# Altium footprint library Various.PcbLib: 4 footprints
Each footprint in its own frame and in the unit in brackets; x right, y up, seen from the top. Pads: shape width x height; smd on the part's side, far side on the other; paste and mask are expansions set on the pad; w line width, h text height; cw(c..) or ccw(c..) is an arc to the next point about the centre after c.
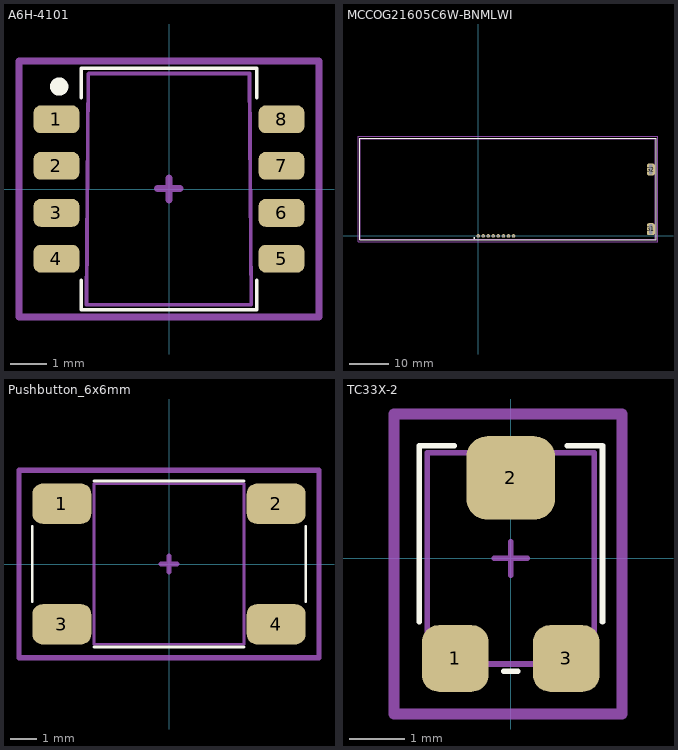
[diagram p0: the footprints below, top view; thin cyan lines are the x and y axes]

## A6H-4101 [mm]
pads (8):
  rrect50% 1.25x0.76 smd paste+0 mask+0.1: 1(-3.075,1.905) 2(-3.075,0.635) 3(-3.075,-0.653) 4(-3.075,-1.905) 5(3.075,-1.905) 6(3.075,-0.653) 7(3.075,0.635) 8(3.075,1.905)
Top Overlay:
  circle w0.3: c-3,2.8 r0.1
  lines w0.1: -2.4,-2.5 -2.4,-3.3 2.4,-3.3 2.4,-2.5 ; -2.4,2.5 -2.4,3.3 2.4,3.3 2.4,2.5
Mechanical 13:
  lines w0.1: -2.205,3.145 -2.255,-3.165 2.24,-3.165 ; -2.195,3.155 2.2,3.155 2.25,-3.155
Component Courtyard:
  lines w0.2: -0.305,0.015 0.295,0.015 ; 0,-0.3 0,0.3 ; -4.1,-3.5 4.1,-3.5 4.1,3.5 -4.1,3.5 -4.1,-3.5
3D body "A6H_4101.step": height 1.55, standoff 0, extent -3.35,-3.16 3.35,3.15

## MCCOG21605C6W-BNMLWI [mm]
pads (10):
  round 0.9 hole 0.6: 1(0,0) 2(1.27,0) 3(2.54,0) 4(3.81,0) 5(5.08,0) 6(6.35,0) 7(7.62,0) 8(8.89,0)
  rrect50% 2x3 hole 0.8 slot 2.5 at 90 deg: G1(43.4,1.7) G2(43.4,16.7)
Top Overlay:
  circle w0.3: c-1,-0.5 r0.1
  lines w0.1: -29.8,-1 44.7,-1 44.7,24.6 -29.8,24.6 -29.8,-1
Mechanical 13:
  lines w0.1: -29.655,-0.8 44.545,-0.8 44.545,24.4 -29.655,24.4 -29.655,-0.8
Component Courtyard:
  lines w0.2: -30.2,-1.4 -30.2,25 45.2,25 45.2,-1.4 -30.2,-1.4
3D body "mccog21605c6w-bnmlwi.stp": height 6.3, standoff -3.3, extent -29.655,-0.8 44.555,24.41

## Pushbutton_6x6mm [mm] "Tactile Switch"
pads (4):
  rrect50% 2.2x1.5 smd: 1(-4,2.25) 2(4,2.25) 3(-4,-2.25) 4(4,-2.25)
Top Overlay:
  lines w0.1: -5.1,-1.4 -5.1,1.4 ; -2.8,-3.1 2.8,-3.1 ; -2.8,3.1 2.8,3.1 ; 5.1,-1.4 5.1,1.4
Mechanical 13:
  lines w0.1: -2.8,-3 2.8,-3 2.8,3 -2.8,3 -2.8,-3
Component Courtyard:
  lines w0.2: -0.3,0 0.3,0 ; 0,-0.3 0,0.3 ; -5.6,-3.5 5.6,-3.5 5.6,3.5 -5.6,3.5 -5.6,-3.5
3D body "PZ_PushButton.stp": height -0.3, standoff -4.7, extent -5,-3 5,3

## TC33X-2 [mm]
pads (3):
  rrect50% 1.2x1.2 smd: 1(-1,-1.8) 3(1,-1.8)
  rrect50% 1.6x1.5 smd: 2(0,1.45)
Top Overlay:
  lines w0.1: -1.651,-1.143 -1.651,2.032 -1.016,2.032 ; -0.127,-2.032 0.127,-2.032 ; 1.016,2.032 1.651,2.032 1.651,-1.143
Mechanical 13:
  lines w0.1: -1.5,-1.9 1.5,-1.9 1.5,1.9 -1.5,1.9 -1.5,-1.9
Component Courtyard:
  lines w0.1: -0.3,0 0.3,0 ; 0,-0.3 0,0.3
  lines w0.2: -2.1,-2.8 2,-2.8 2,2.6 -2.1,2.6 -2.1,-2.8
3D body "TC33X-2-502E.STEP": height 1.21, standoff 0.01, extent -1.5,-1.9 1.5,1.9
